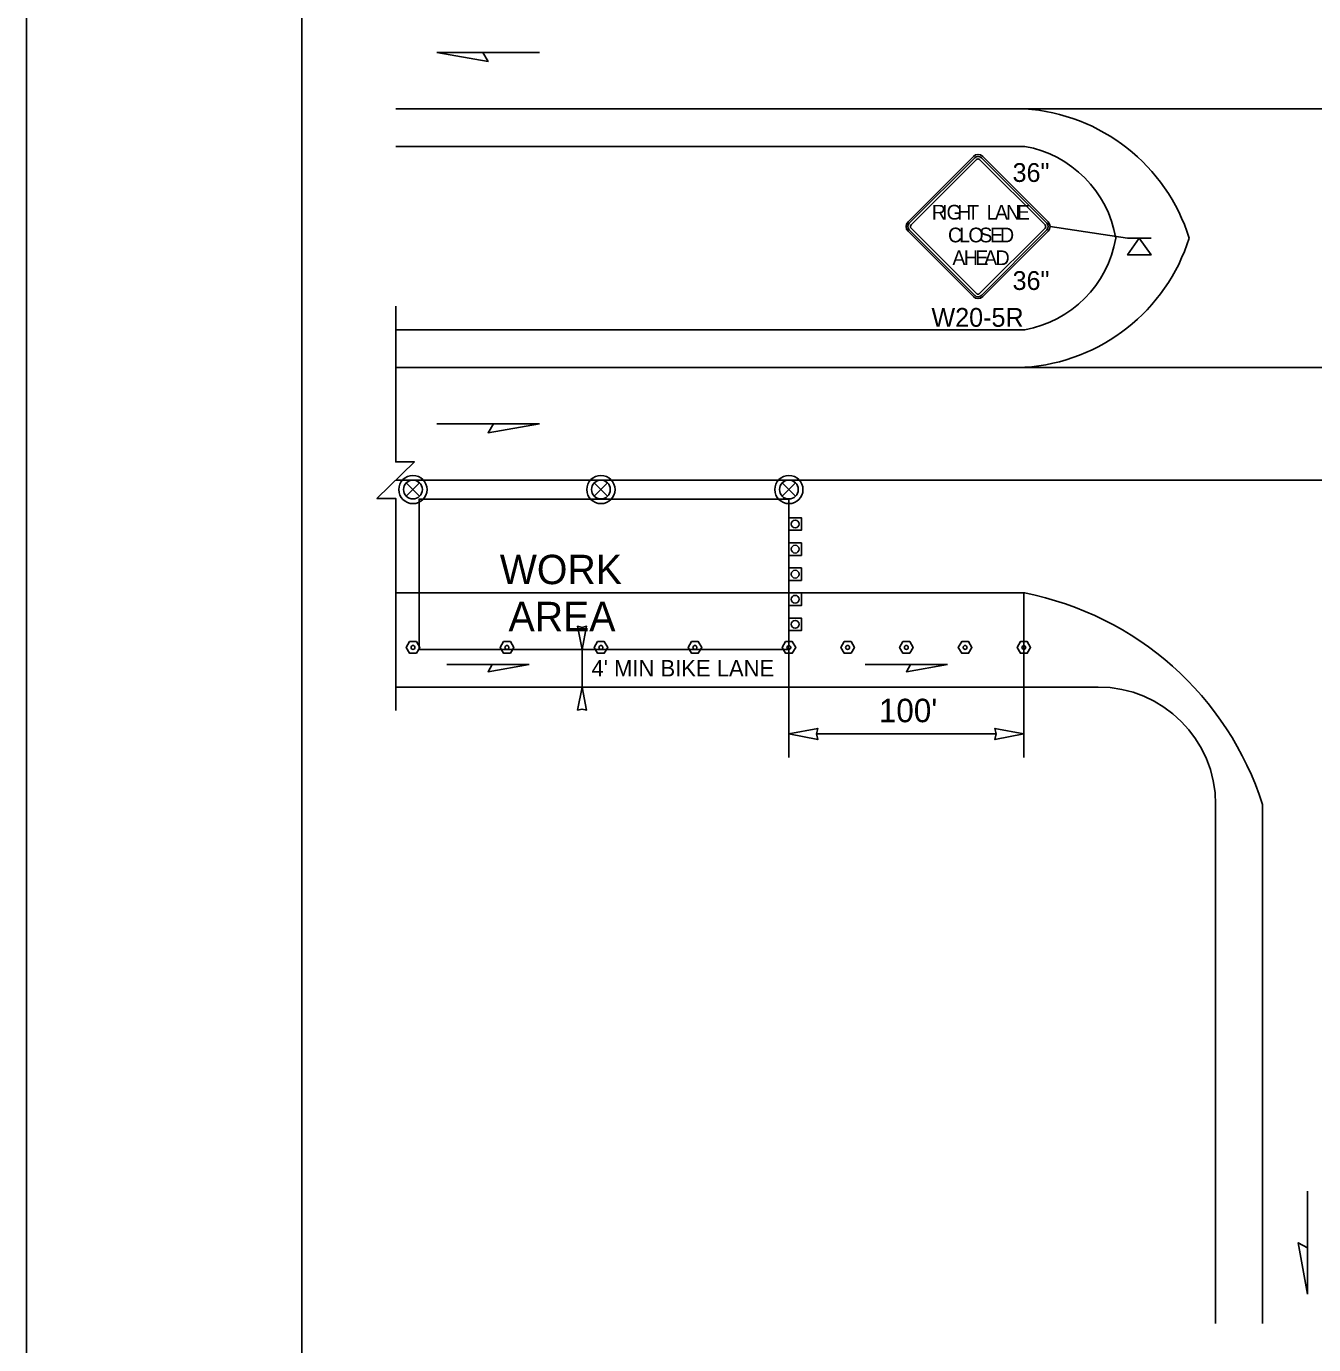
# Model space of a CAD drawing. Extents: x 99958 to 100136, y 99935 to 100013.
# Drawn here: x 100039.062 to 100043.446, y 99971.834 to 99976.321 of the extents above; entities that cross this region are included whole.
import ezdxf

# ---------------------------------------------------------------- set-up
doc = ezdxf.new("R2010")
doc.units = 0
for name, color, linetype in [('RD_ED_ShoulderPavedEdge', 7, 'Continuous'), ('RD_MK_LineEdgeWhite', 7, 'Continuous'), ('RD_MK_LineEdgeYellow', 7, 'Continuous'), ('RD_MK_LineLane', 7, 'Continuous'), ('SH_GI_PlotLimits', 7, 'Continuous'), ('SH_GI_SheetBorder', 7, 'Continuous'), ('TR_SN_ConstructionSigns', 7, 'Continuous'), ('TR_WZ_PortableSignMountBlk-Org', 7, 'Continuous'), ('TR_WZ_TrafficCone', 7, 'Continuous'), ('TR_WZ_TrafficSafetyDrum', 7, 'Continuous'), ('TR_WZ_TubularMarker', 7, 'Continuous'), ('TR_WZ_WorkAreaLabel', 7, 'Continuous'), ('TR_WZ_WorkZoneDetails', 7, 'Continuous'), ('TR_WZ_WorkZoneTextCurrent', 7, 'Continuous')]:
    doc.layers.add(name, color=color, linetype=linetype)

msp = doc.modelspace()

# ---------------------------------------------------------------- linework, layer by layer
at = {"layer": 'RD_ED_ShoulderPavedEdge'}
for p, q in [((100040.32, 99975.9124), (100042.4619, 99975.9124)), ((100040.32, 99975.2885), (100042.4619, 99975.2885)), ((100040.32, 99974.0724), (100042.7119, 99974.0724))]:
    msp.add_line(p, q, dxfattribs=at)
msp.add_lwpolyline([(100043.1119, 99971.9059), (100043.1119, 99973.6724)], dxfattribs=at)
for centre, radius, start, end in [((100042.3952, 99975.5361), 0.3822, 9.6882, 79.9433), ((100042.3952, 99975.6648), 0.3822, 280.0567, 350.3118), ((100042.7119, 99973.6724), 0.4, 0, 90)]:
    msp.add_arc(centre, radius, start, end, dxfattribs=at)
at = {"layer": 'RD_MK_LineEdgeWhite'}
msp.add_line((100043.2719, 99973.6724), (100043.2719, 99971.9059), dxfattribs=at)
msp.add_arc((100042.257, 99973.3462), 1.0661, 17.8172, 78.9158, dxfattribs=at)
at = {"layer": 'RD_MK_LineEdgeYellow'}
for p, q in [((100040.32, 99976.0404), (100042.4619, 99976.0404)), ((100042.4619, 99976.0404), (100044.8819, 99976.0404)), ((100040.32, 99975.1604), (100042.4619, 99975.1604)), ((100042.4619, 99975.1604), (100044.8819, 99975.1604)), ((100040.32, 99974.3924), (100042.4619, 99974.3924))]:
    msp.add_line(p, q, dxfattribs=at)
for centre, start, end in [((100042.4204, 99975.4112), 17.4622, 86.2234), ((100042.4204, 99975.7897), 273.7766, 342.5378)]:
    msp.add_arc(centre, 0.6306, start, end, dxfattribs=at)
at = {"layer": 'RD_MK_LineLane'}
msp.add_lwpolyline([(100047.555, 99974.7765), (100040.32, 99974.7765)], dxfattribs=at)
at = {"layer": 'SH_GI_PlotLimits'}
msp.add_lwpolyline([(100039.0625, 99969.6875), (100056.0625, 99969.6875), (100056.0625, 99980.6875), (100039.0625, 99980.6875)], close=True, dxfattribs=at)
at = {"layer": 'SH_GI_SheetBorder'}
msp.add_line((100040, 99980.375), (100040, 99970), dxfattribs=at)
at = {"layer": 'TR_SN_ConstructionSigns'}
for p, q in [((100042.2872, 99975.8783), (100042.0645, 99975.6556)), ((100042.2916, 99975.8739), (100042.0689, 99975.6512)), ((100042.0751, 99975.645), (100042.2978, 99975.8677)), ((100042.3084, 99975.8677), (100042.5312, 99975.645)), ((100042.5374, 99975.6512), (100042.3146, 99975.8739)), ((100042.5418, 99975.6556), (100042.319, 99975.8783)), ((100042.2978, 99975.4116), (100042.0751, 99975.6344)), ((100042.5312, 99975.6344), (100042.3084, 99975.4116)), ((100042.0645, 99975.6238), (100042.2872, 99975.401)), ((100042.0689, 99975.6282), (100042.2916, 99975.4055)), ((100042.3146, 99975.4055), (100042.5374, 99975.6282)), ((100042.319, 99975.401), (100042.5418, 99975.6238))]:
    msp.add_line(p, q, dxfattribs=at)
for centre, radius, start, end in [((100042.3031, 99975.8624), 0.0225, 45, 135), ((100042.3031, 99975.8624), 0.0162, 45, 135), ((100042.3031, 99975.8624), 0.0075, 45, 135), ((100042.0804, 99975.6397), 0.0225, 135, 225), ((100042.0804, 99975.6397), 0.0162, 135, 225), ((100042.0804, 99975.6397), 0.0075, 135, 225), ((100042.5259, 99975.6397), 0.0075, 315, 45), ((100042.5259, 99975.6397), 0.0162, 315, 45), ((100042.5259, 99975.6397), 0.0225, 315, 45), ((100042.3031, 99975.417), 0.0075, 225, 315), ((100042.3031, 99975.417), 0.0225, 225, 315), ((100042.3031, 99975.417), 0.0162, 225, 315)]:
    msp.add_arc(centre, radius, start, end, dxfattribs=at)
at = {"layer": 'TR_WZ_PortableSignMountBlk-Org'}
msp.add_line((100042.8119, 99975.6004), (100042.8919, 99975.6004), dxfattribs=at)
msp.add_lwpolyline([(100042.8519, 99975.6004), (100042.8919, 99975.543), (100042.8119, 99975.543)], close=True, dxfattribs=at)
at = {"layer": 'TR_WZ_TrafficCone'}
for points in [[(100041.7016, 99974.6485), (100041.7016, 99974.6058), (100041.6589, 99974.6058), (100041.6589, 99974.6485), (100041.7016, 99974.6485)], [(100041.6589, 99974.6485), (100041.6589, 99974.6058), (100041.7016, 99974.6058), (100041.7016, 99974.6485), (100041.6589, 99974.6485)], [(100041.7016, 99974.5631), (100041.7016, 99974.5205), (100041.6589, 99974.5205), (100041.6589, 99974.5631), (100041.7016, 99974.5631)], [(100041.6589, 99974.5631), (100041.6589, 99974.5205), (100041.7016, 99974.5205), (100041.7016, 99974.5631), (100041.6589, 99974.5631)], [(100041.7016, 99974.4778), (100041.7016, 99974.4351), (100041.6589, 99974.4351), (100041.6589, 99974.4778), (100041.7016, 99974.4778)], [(100041.6589, 99974.4778), (100041.6589, 99974.4351), (100041.7016, 99974.4351), (100041.7016, 99974.4778), (100041.6589, 99974.4778)], [(100041.7016, 99974.3924), (100041.7016, 99974.3498), (100041.6589, 99974.3498), (100041.6589, 99974.3924), (100041.7016, 99974.3924)], [(100041.6589, 99974.3924), (100041.6589, 99974.3498), (100041.7016, 99974.3498), (100041.7016, 99974.3924), (100041.6589, 99974.3924)], [(100041.7016, 99974.3071), (100041.7016, 99974.2644), (100041.6589, 99974.2644), (100041.6589, 99974.3071), (100041.7016, 99974.3071)], [(100041.6589, 99974.3071), (100041.6589, 99974.2644), (100041.7016, 99974.2644), (100041.7016, 99974.3071), (100041.6589, 99974.3071)]]:
    msp.add_lwpolyline(points, dxfattribs=at)
for centre in [(100041.6803, 99974.6271), (100041.6803, 99974.5418), (100041.6803, 99974.4565), (100041.6803, 99974.3711), (100041.6803, 99974.2858)]:
    msp.add_circle(centre, 0.0133, dxfattribs=at)
at = {"layer": 'TR_WZ_TrafficSafetyDrum'}
for p, q in [((100040.3563, 99974.7671), (100040.4015, 99974.7218)), ((100040.4015, 99974.7671), (100040.3563, 99974.7218)), ((100040.9963, 99974.7671), (100041.0415, 99974.7218)), ((100041.0415, 99974.7671), (100040.9963, 99974.7218)), ((100041.6363, 99974.7671), (100041.6815, 99974.7218)), ((100041.6815, 99974.7671), (100041.6363, 99974.7218))]:
    msp.add_line(p, q, dxfattribs=at)
for centre, radius in [((100040.3789, 99974.7445), 0.048), ((100040.3789, 99974.7445), 0.048), ((100041.0189, 99974.7445), 0.048), ((100041.0189, 99974.7445), 0.048), ((100041.6589, 99974.7445), 0.048), ((100041.6589, 99974.7445), 0.048), ((100040.3789, 99974.7445), 0.032), ((100041.0189, 99974.7445), 0.032), ((100041.6589, 99974.7445), 0.032)]:
    msp.add_circle(centre, radius, dxfattribs=at)
at = {"layer": 'TR_WZ_TubularMarker'}
for points in [[(100040.3558, 99974.2071), (100040.3674, 99974.2271), (100040.3905, 99974.2271), (100040.402, 99974.2071), (100040.3905, 99974.1871), (100040.3674, 99974.1871)], [(100040.6758, 99974.2071), (100040.6874, 99974.2271), (100040.7105, 99974.2271), (100040.722, 99974.2071), (100040.7105, 99974.1871), (100040.6874, 99974.1871)], [(100040.9958, 99974.2071), (100041.0074, 99974.2271), (100041.0305, 99974.2271), (100041.042, 99974.2071), (100041.0305, 99974.1871), (100041.0074, 99974.1871)], [(100041.3158, 99974.2071), (100041.3274, 99974.2271), (100041.3505, 99974.2271), (100041.362, 99974.2071), (100041.3505, 99974.1871), (100041.3274, 99974.1871)], [(100041.6358, 99974.2071), (100041.6474, 99974.2271), (100041.6705, 99974.2271), (100041.682, 99974.2071), (100041.6705, 99974.1871), (100041.6474, 99974.1871)], [(100041.6358, 99974.2071), (100041.6474, 99974.2271), (100041.6705, 99974.2271), (100041.682, 99974.2071), (100041.6705, 99974.1871), (100041.6474, 99974.1871)], [(100041.8358, 99974.2071), (100041.8474, 99974.2271), (100041.8705, 99974.2271), (100041.882, 99974.2071), (100041.8705, 99974.1871), (100041.8474, 99974.1871)], [(100042.0358, 99974.2071), (100042.0474, 99974.2271), (100042.0705, 99974.2271), (100042.082, 99974.2071), (100042.0705, 99974.1871), (100042.0474, 99974.1871)], [(100042.2358, 99974.2071), (100042.2474, 99974.2271), (100042.2705, 99974.2271), (100042.282, 99974.2071), (100042.2705, 99974.1871), (100042.2474, 99974.1871)], [(100042.4358, 99974.2071), (100042.4474, 99974.2271), (100042.4705, 99974.2271), (100042.482, 99974.2071), (100042.4705, 99974.1871), (100042.4474, 99974.1871)]]:
    msp.add_lwpolyline(points, close=True, dxfattribs=at)
for points in [[(100040.3674, 99974.1871), (100040.3905, 99974.1871), (100040.402, 99974.2071), (100040.3905, 99974.2271), (100040.3674, 99974.2271), (100040.3558, 99974.2071), (100040.3674, 99974.1871)], [(100040.6874, 99974.1871), (100040.7105, 99974.1871), (100040.722, 99974.2071), (100040.7105, 99974.2271), (100040.6874, 99974.2271), (100040.6758, 99974.2071), (100040.6874, 99974.1871)], [(100041.0074, 99974.1871), (100041.0305, 99974.1871), (100041.042, 99974.2071), (100041.0305, 99974.2271), (100041.0074, 99974.2271), (100040.9958, 99974.2071), (100041.0074, 99974.1871)], [(100041.3274, 99974.1871), (100041.3505, 99974.1871), (100041.362, 99974.2071), (100041.3505, 99974.2271), (100041.3274, 99974.2271), (100041.3158, 99974.2071), (100041.3274, 99974.1871)], [(100041.6474, 99974.1871), (100041.6705, 99974.1871), (100041.682, 99974.2071), (100041.6705, 99974.2271), (100041.6474, 99974.2271), (100041.6358, 99974.2071), (100041.6474, 99974.1871)], [(100041.6474, 99974.1871), (100041.6705, 99974.1871), (100041.682, 99974.2071), (100041.6705, 99974.2271), (100041.6474, 99974.2271), (100041.6358, 99974.2071), (100041.6474, 99974.1871)], [(100041.8474, 99974.1871), (100041.8705, 99974.1871), (100041.882, 99974.2071), (100041.8705, 99974.2271), (100041.8474, 99974.2271), (100041.8358, 99974.2071), (100041.8474, 99974.1871)], [(100042.0474, 99974.1871), (100042.0705, 99974.1871), (100042.082, 99974.2071), (100042.0705, 99974.2271), (100042.0474, 99974.2271), (100042.0358, 99974.2071), (100042.0474, 99974.1871)], [(100042.2474, 99974.1871), (100042.2705, 99974.1871), (100042.282, 99974.2071), (100042.2705, 99974.2271), (100042.2474, 99974.2271), (100042.2358, 99974.2071), (100042.2474, 99974.1871)], [(100042.4474, 99974.1871), (100042.4705, 99974.1871), (100042.482, 99974.2071), (100042.4705, 99974.2271), (100042.4474, 99974.2271), (100042.4358, 99974.2071), (100042.4474, 99974.1871)]]:
    msp.add_lwpolyline(points, dxfattribs=at)
for centre in [(100040.3789, 99974.2071), (100040.6989, 99974.2071), (100041.0189, 99974.2071), (100041.3389, 99974.2071), (100041.6589, 99974.2071), (100041.6589, 99974.2071), (100041.8589, 99974.2071), (100042.0589, 99974.2071), (100042.2589, 99974.2071), (100042.4589, 99974.2071)]:
    msp.add_circle(centre, 0.00667, dxfattribs=at)
at = {"layer": 'TR_WZ_WorkZoneDetails'}
for p, q in [((100040.6169, 99976.2324), (100040.8098, 99976.2324)), ((100042.5484, 99975.6397), (100042.8119, 99975.6004)), ((100040.6526, 99974.9685), (100040.4597, 99974.9685)), ((100042.4589, 99974.3924), (100042.4589, 99973.8325)), ((100041.0189, 99974.2004), (100040.8909, 99974.2004)), ((100040.9549, 99974.0724), (100040.9549, 99974.2004)), ((100041.6589, 99974.2004), (100041.6589, 99973.8325)), ((100040.649, 99974.1488), (100040.4947, 99974.1488)), ((100042.0732, 99974.1488), (100041.9189, 99974.1488)), ((100041.0189, 99974.0724), (100040.8909, 99974.0724)), ((100042.3652, 99973.9125), (100041.7526, 99973.9125)), ((100043.4242, 99972.1631), (100043.4242, 99972.356))]:
    msp.add_line(p, q, dxfattribs=at)
for points in [[(100040.4597, 99976.2324), (100040.6347, 99976.2016), (100040.6169, 99976.2324)], [(100040.8098, 99974.9685), (100040.6347, 99974.9376), (100040.6526, 99974.9685)], [(100040.4, 99974.2004), (100040.4, 99974.7114), (100041.6589, 99974.7114), (100041.6589, 99974.2004)], [(100040.9549, 99974.2004), (100040.9703, 99974.2791), (100040.9549, 99974.2754), (100040.9395, 99974.2791)], [(100040.7748, 99974.1488), (100040.6347, 99974.1241), (100040.649, 99974.1488)], [(100042.199, 99974.1488), (100042.0589, 99974.1241), (100042.0732, 99974.1488)], [(100040.9549, 99974.0724), (100040.9703, 99973.9938), (100040.9549, 99973.9975), (100040.9395, 99973.9938)], [(100041.6589, 99973.9125), (100041.7572, 99973.9317), (100041.7526, 99973.9125), (100041.7572, 99973.8932)], [(100042.4589, 99973.9125), (100042.3606, 99973.9317), (100042.3652, 99973.9125), (100042.3606, 99973.8932)], [(100043.4242, 99972.0059), (100043.3933, 99972.181), (100043.4242, 99972.1631)]]:
    msp.add_lwpolyline(points, close=True, dxfattribs=at)
msp.add_lwpolyline([(100040.32, 99973.9925), (100040.32, 99974.7145), (100040.256, 99974.7145), (100040.384, 99974.8384), (100040.32, 99974.8384), (100040.32, 99975.3685)], dxfattribs=at)

# ---------------------------------------------------------------- texts
at = {"layer": 'TR_SN_ConstructionSigns'}
for s, p in [('36"', (100042.4205, 99975.7915)), ('36"', (100042.4205, 99975.4238)), ('W20-5R', (100042.1443, 99975.2985))]:
    msp.add_text(s, height=0.064, rotation=360, dxfattribs=at).set_placement(p)
for s, p in [('R', (100042.1456, 99975.6634)), ('I', (100042.1806, 99975.6634)), ('G', (100042.1958, 99975.6634)), ('H', (100042.2321, 99975.6634)), ('T', (100042.2658, 99975.6634)), ('L', (100042.3324, 99975.6634)), ('A', (100042.3603, 99975.6634)), ('N', (100042.3981, 99975.6634)), ('E', (100042.4351, 99975.6634)), ('C', (100042.2006, 99975.5859)), ('L', (100042.2386, 99975.5859)), ('O', (100042.2701, 99975.5859)), ('S', (100042.3071, 99975.5859)), ('E', (100042.3436, 99975.5859)), ('D', (100042.3776, 99975.5859)), ('A', (100042.2156, 99975.5084)), ('H', (100042.2546, 99975.5084)), ('E', (100042.2936, 99975.5084)), ('A', (100042.3236, 99975.5084)), ('D', (100042.3626, 99975.5084))]:
    msp.add_text(s, height=0.05, dxfattribs=at).set_placement(p)
at = {"layer": 'TR_WZ_WorkAreaLabel'}
for s, p in [('WORK', (100040.6746, 99974.4225)), ('AREA', (100040.7043, 99974.2624))]:
    msp.add_text(s, height=0.1, dxfattribs=at).set_placement(p)
at = {"layer": 'TR_WZ_WorkZoneTextCurrent'}
msp.add_text("4' MIN BIKE LANE", height=0.056, dxfattribs=at).set_placement((100040.9869, 99974.1084))
msp.add_text("100'", height=0.08, rotation=360, dxfattribs=at).set_placement((100041.9653, 99973.9525))

doc.saveas('drawing.dxf')
